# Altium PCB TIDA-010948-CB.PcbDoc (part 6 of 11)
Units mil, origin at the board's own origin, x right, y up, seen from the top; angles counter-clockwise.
Board outline 8100 x 8400 mil, 8 copper layers (L01 - TOP, L02 - GND, L03 - SIG, L04 - GND, L05 - PWR, L06 - SIG, L07 - GND, L08 - BOTTOM), stack 59.656 mil thick; 711 components, 572 nets, 2646 pads, 1325 vias.
Unrouted connection lines stored in the file: 988.
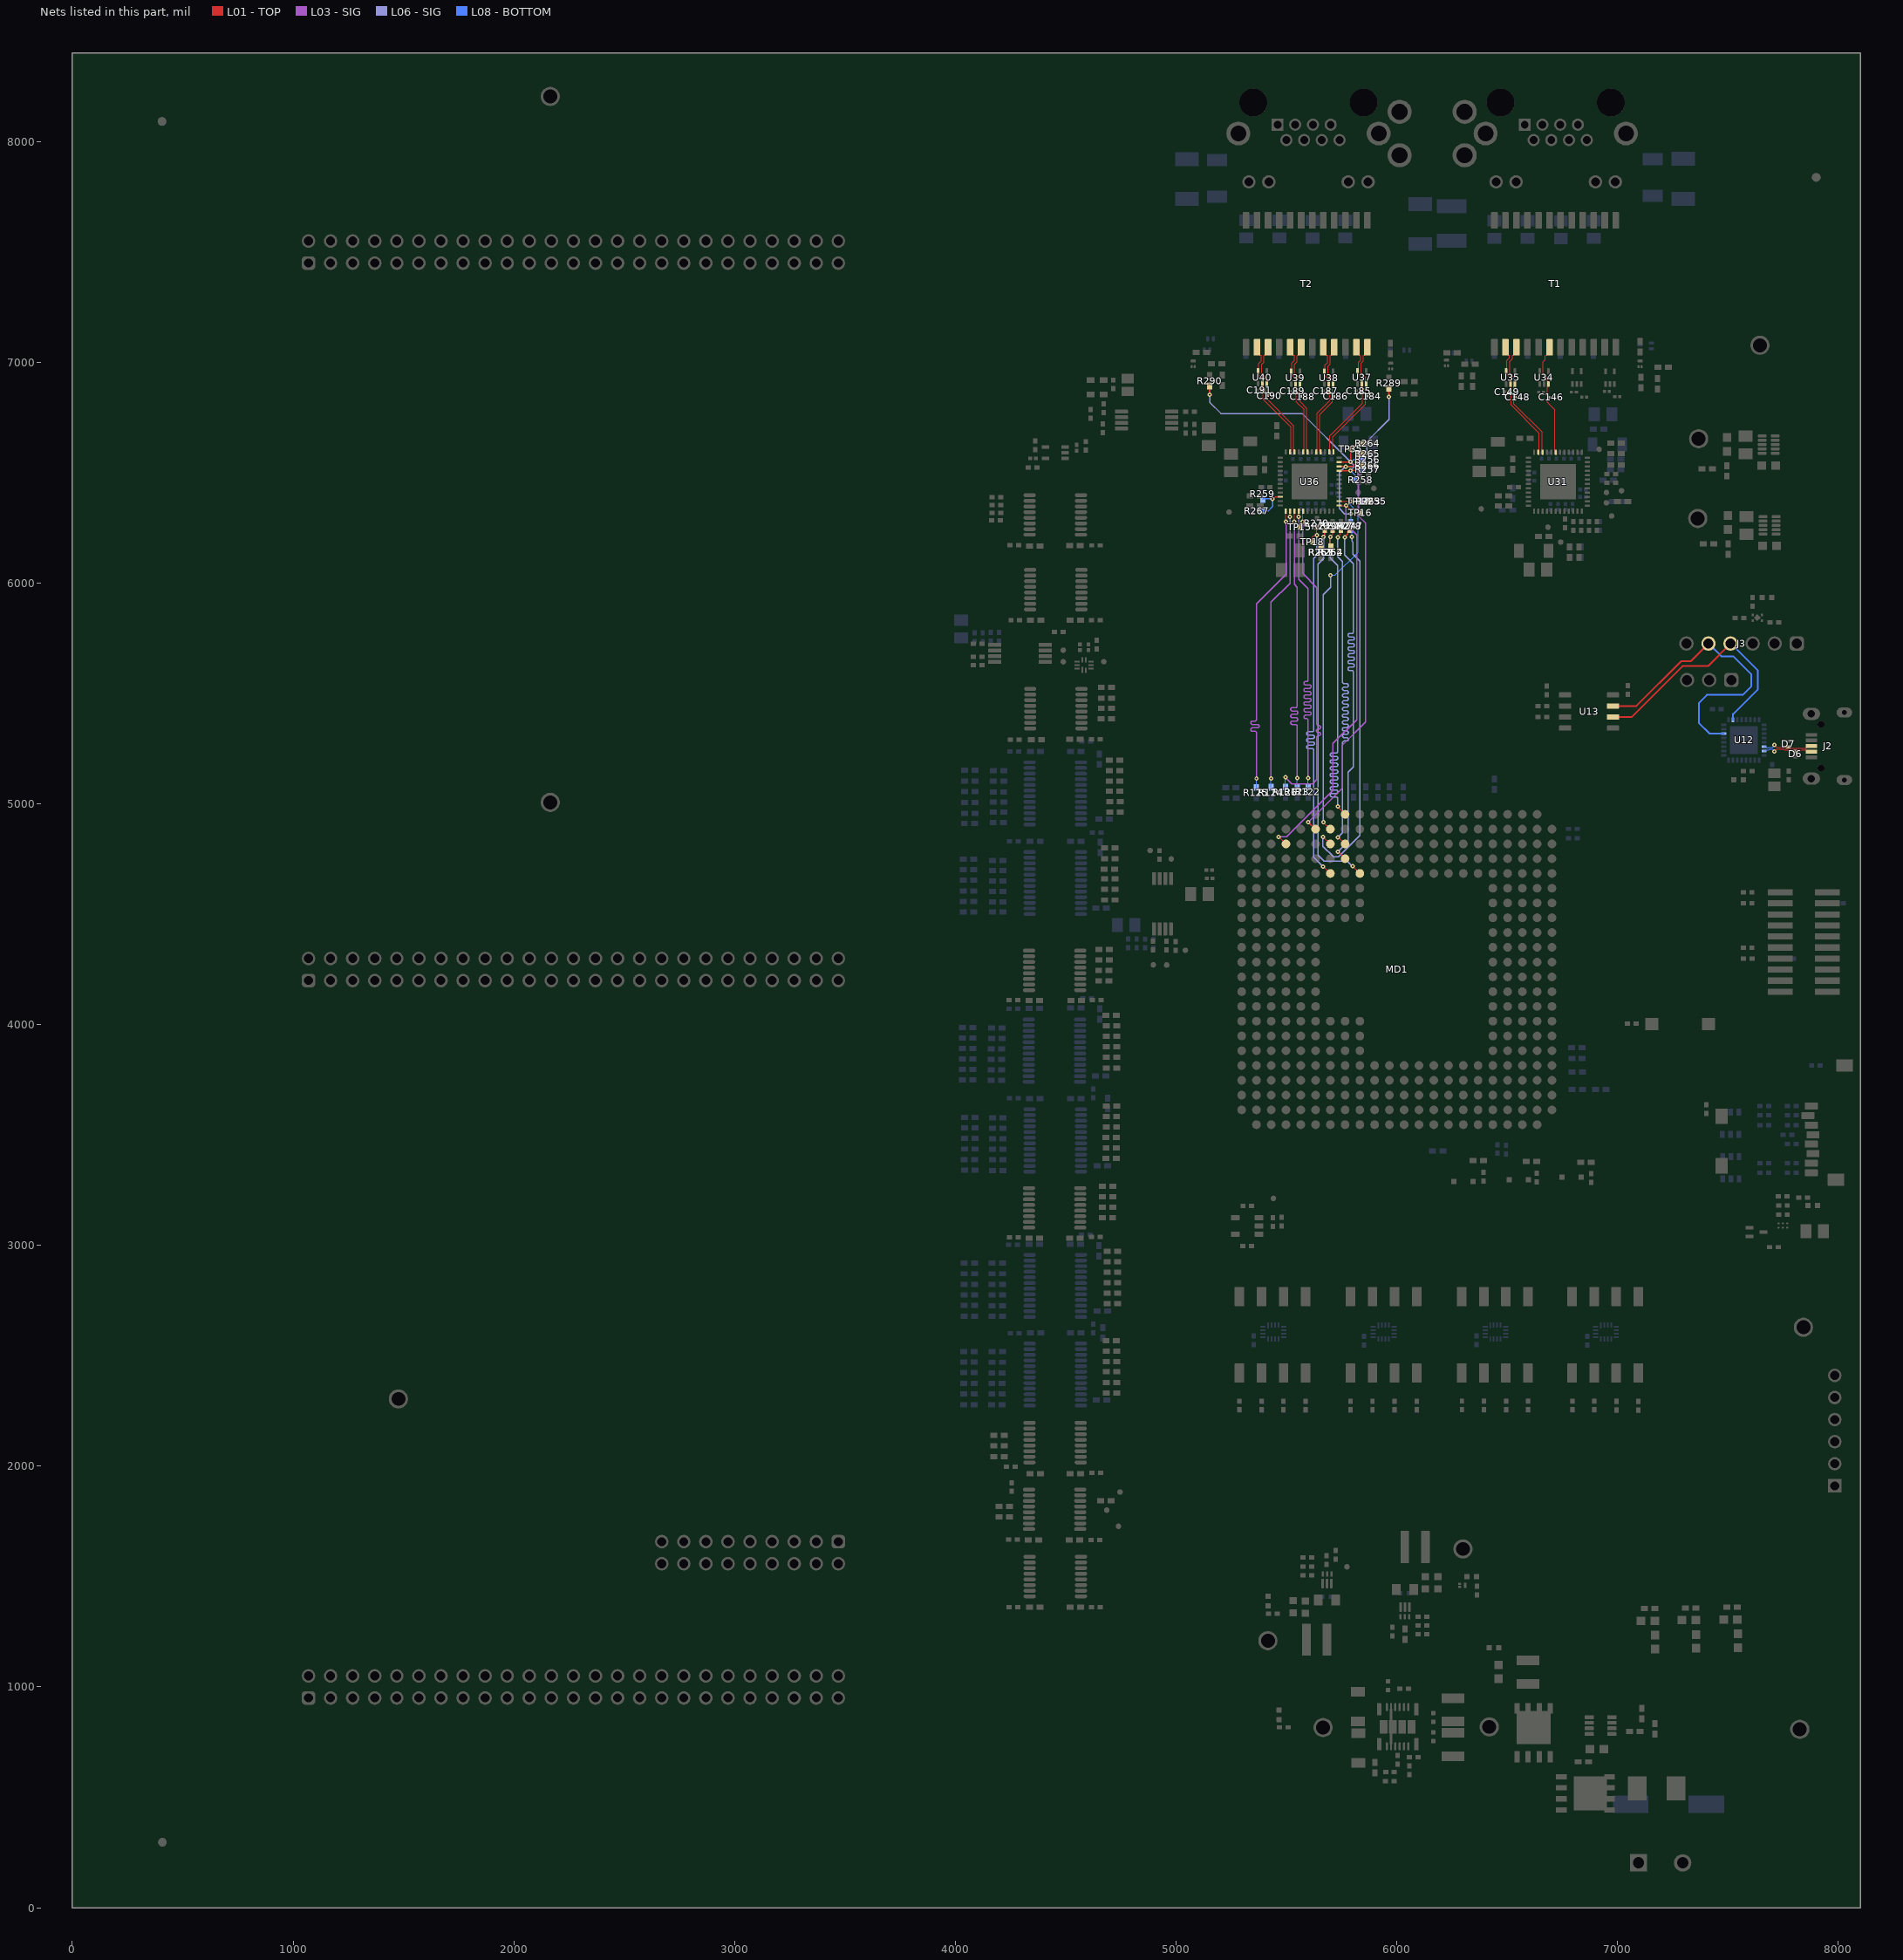
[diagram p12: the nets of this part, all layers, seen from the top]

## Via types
v1: diameter 19.68, hole 7.87, L01 - TOP to L08 - BOTTOM, 1310 vias
v2: diameter 20, hole 7.87, L01 - TOP to L08 - BOTTOM, tented both sides, 7 vias
v3: diameter 200, hole 144, L01 - TOP to L08 - BOTTOM, 6 vias
v4: diameter 20, hole 8, L01 - TOP to L08 - BOTTOM, tented both sides, 2 vias

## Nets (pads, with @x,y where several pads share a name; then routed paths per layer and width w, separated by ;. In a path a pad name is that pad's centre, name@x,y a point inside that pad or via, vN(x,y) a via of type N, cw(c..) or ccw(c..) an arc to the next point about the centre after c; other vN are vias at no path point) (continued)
ETH1_TD_C_P: C146.2 T1.6 U31.7 U34.3 | length 534.9
  L01 - TOP w3.5: U34.3@6682.5,6901.37 C146.2@6682.5,6841.5 ; U34.3@6686.19,6901.37 6682.56,6901.37 6682.5,6901.42 6682.5,6927 6662.5,6947 6662.5,7001.57 6673.25,7012.32 6673.25,7030.4 6675.3,7032.45 6678.8,7032.45 6692,7045.65 T1.6@6692,7067.5 ; C146.2@6688.48,6841.5 C146.2@6682.5,6841.5 ; C146.2@6682.5,6841.5 6682.5,6818 6716.56,6783.94 6716.56,6604.97 U31.7@6717.33,6604.21 ; U31.7@6717.33,6595.69 U31.7@6720.16,6592.86 U31.7@6717.33,6595.69 ; U31.7@6717.33,6595.69 U31.7@6717.33,6604.21 ; U31.7@6717.33,6595.69 U31.7@6717.33,6604.21
ETH1_TD_D_N: C149.2 T1.2 U31.11 U35.2 U35.5 | length 577.5
  L01 - TOP w3.5: T1.2@6492,7067.5 6492,7045.65 6505.2,7032.45 6508.7,7032.45 6510.75,7030.4 6510.75,7020.5 6499,7008.75 U35.5@6499,6959.58 ; U35.5@6494.81,6959.63 6494.87,6959.58 U35.5@6499,6959.58 ; C149.2@6512.02,6866 C149.2@6518,6866 ; U35.2@6514.5,6901.37 6514.56,6901.42 U35.2@6518,6901.42 ; U35.5@6499,6959.58 6499,6944.32 6518,6925.32 U35.2@6518,6901.42 ; C149.2@6518,6866 U35.2@6518,6901.42 ; C149.2@6518,6866 6518,6805.82 6645.01,6678.81 6645.01,6604.97 U31.11@6644.25,6604.21 ; U31.11@6644.25,6595.69 U31.11@6641.42,6592.86 U31.11@6644.25,6595.69 ; U31.11@6644.25,6595.69 U31.11@6644.25,6604.21 ; U31.11@6644.25,6595.69 U31.11@6644.25,6604.21
ETH1_TD_D_P: C148.2 T1.3 U31.10 U35.3 | length 573.4
  L01 - TOP w3.5: U35.3@6530.5,6901.37 C148.2@6530.5,6843 ; U35.3@6534.19,6901.37 6530.56,6901.37 6530.5,6901.42 6530.5,6930.5 6511.5,6949.5 6511.5,7003.57 6523.25,7015.32 6523.25,7030.4 6525.3,7032.45 6528.8,7032.45 6542,7045.65 T1.3@6542,7067.5 ; C148.2@6536.48,6843 C148.2@6530.5,6843 ; C148.2@6530.5,6843 6530.5,6811 6657.51,6683.99 6657.51,6604.97 U31.10@6658.27,6604.21 ; U31.10@6658.27,6595.69 U31.10@6661.1,6592.86 U31.10@6658.27,6595.69 ; U31.10@6658.27,6595.69 U31.10@6658.27,6604.21 ; U31.10@6658.27,6595.69 U31.10@6658.27,6604.21
ETH2_GPIO_1: R259.1 R267.2 U36.22 | length 173.3
  L01 - TOP w6: v1(5437,6381) 5440.7,6381 5450.28,6390.57 U36.22@5471.28,6390.57
  L08 - BOTTOM w6: R267.2@5389.62,6326 5416.5,6326 5437,6346.5 v1(5437,6381) 5394.62,6381 R259.1@5393,6379.38
ETH2_LED_0: MD1.B6 R256.1 R264.2 R290.1 TP35.1 U36.47 | length 2871.7
  L01 - TOP w6: v1(5599,4916.5) 5599.91,4916.5 5630.98,4885.43 MD1.B6@5631.89,4885.43 ; U36.47@5739.03,6548.03 v1(5791,6548) v1@5789.5,6549.5 ; v1(5791,6548) 5791.25,6548.25 5791.25,6606.25 TP35.1@5791.5,6606.5 5817.5,6632.5 R264.2@5844.88,6632.5
  L01 - TOP w8: v1(5152.5,6853) 5152.75,6853.25 5152.75,6891.63 R290.1@5153,6891.88
  L03 - SIG w6: v1(5599,4916.5) 5754.5,5072 5754.5,5266.54 5858,5370.04 5858,6272 5825.81,6304.19 5825.81,6513.19 v1(5791,6548)
  L06 - SIG w6: v1(5152.5,6853) 5152.5,6818.5 5203,6768 5571,6768 v1(5791,6548)
  L08 - BOTTOM w6: v1(5791,6548) 5793.65,6548 5805.65,6560 R256.1@5844.38,6560
ETH2_LED_1: R247.1 R257.1 R265.2 U36.46 | length 527.5
  L01 - TOP w6: U36.46@5739,6528.37 5739.19,6528.19 5768.31,6528.19 v1(5768.5,6528) 5769.5,6529 5802,6529 5812,6539 5812,6556 5818.5,6562.5 5818.5,6574.5 5820.69,6576.69 5835.57,6576.69 R265.2@5844.38,6585.5
  L06 - SIG w5.25: v1(5768.5,6528) 5740.03,6499.53 5740.03,6337.47 5764,6313.5 v1(5792.5,6313.5)
  L08 - BOTTOM w4.25: R247.1@5792,6278.69 5792.5,6279.19 v1(5792.5,6313.5)
  L08 - BOTTOM w6: v1(5768.5,6528) 5805.57,6528 5818.79,6514.78 5844.16,6514.78 R257.1@5844.38,6515
ETH2_LED_2: R258.1 R266.2 R289.1 U36.45 | length 614.7
  L01 - TOP w6: U36.45@5739,6508.69 5739.41,6509.09 5789.59,6509.09 v1(5790,6509.5) 5811.5,6509.5 5821,6519 5821,6523 5821.19,6523.19 5836.07,6523.19 R266.2@5844.88,6532
  L01 - TOP w8: R289.1@5964.5,6881.88 5964.75,6881.63 5964.75,6842.75 v1(5965,6842.5)
  L06 - SIG w6: v1(5790,6509.5) 5863.81,6583.31 5863.81,6639.81 5965,6741 v1(5965,6842.5)
  L08 - BOTTOM w6: v1(5790,6509.5) 5812.38,6487.12 R258.1@5812.38,6467
ETH2_RGMII2_RD0: MD1.E9 R253.1 R261.2 R273.1 | length 1808.7
  L01 - TOP w4.25: v1(5800,4717) 5800.16,4717 5832.52,4684.64 MD1.E9@5832.68,4684.64
  L01 - TOP w5.25: v1(5668,6208.5) 5668,6212.41 5673,6217.41 R273.1@5673,6238.31
  L01 - TOP w6: R261.2@5656.5,6162.62 5658.5,6164.62 5658.5,6195.3 5668,6204.8 v1(5668,6208.5)
  L06 - SIG w5.25: v1(5668,6208.5) 5668,6111.69 5642.83,6086.52 5642.83,4767.93 5670.13,4740.64 5776.36,4740.64 v1(5800,4717)
  L08 - BOTTOM w6: R253.1@5658.5,6161.62 5658.5,6195.3 5668,6204.8 v1(5668,6208.5)
ETH2_RGMII2_RD1: MD1.A8 R254.1 R262.2 R274.1 | length 1805.9
  L01 - TOP w4.25: v1(5699,6208.5) 5699,6210.13 5709.5,6220.63 R274.1@5709.5,6238.81 ; v1(5732,4987.5) 5732,4986.8 MD1.A8@5764.75,4954.05
  L01 - TOP w6: v1(5699,6208.5) 5699,6164.62 R262.2@5700.5,6163.12 ; MD1.A8@5764.75,4954.05 5764.75,4953.36 MD1.A8@5765.75,4952.36
  L06 - SIG w5.25: v1(5699,6208.5) 5699,6112.91 5732,6079.91 5732,5276.61 5732,5237.34 cw(c5724.38,5237.34) 5724.38,5229.72 5705.88,5229.72 ccw(c5705.88,5222.09) 5705.88,5214.47 5725.41,5214.47 cw(c5725.41,5206.84) 5725.41,5199.22 5705.88,5199.22 ccw(c5705.88,5191.59) 5705.88,5183.97 5725.41,5183.97 cw(c5725.41,5176.34) 5725.41,5168.72 5705.88,5168.72 ccw(c5705.88,5161.09) 5705.88,5153.47 5725.41,5153.47 cw(c5725.41,5145.84) 5725.41,5138.22 5705.88,5138.22 ccw(c5705.88,5130.59) 5705.88,5122.97 5725.41,5122.97 cw(c5725.41,5115.34) 5725.41,5107.72 5705.88,5107.72 ccw(c5705.88,5100.09) 5705.88,5092.47 5725.41,5092.47 cw(c5725.41,5084.84) 5725.41,5077.22 5705.88,5077.22 ccw(c5705.88,5069.59) 5705.88,5061.97 5725.41,5061.97 cw(c5725.41,5054.34) 5725.41,5046.72 5705.88,5046.72 ccw(c5705.88,5039.09) 5705.88,5031.47 5724.38,5031.47 cw(c5724.38,5023.84) 5732,5023.84 5732,5021.22 v1(5732,4987.5)
  L08 - BOTTOM w6: v1(5699,6208.5) 5699,6164.62 R254.1@5702,6161.62
ETH2_RGMII2_RD2: MD1.C8 R277.1 | length 1816.4
  L01 - TOP w4.25: v1(5732.5,6207.5) 5746.5,6221.5 R277.1@5746.5,6238.81 ; v1(5733.5,4848.5) 5734.62,4848.5 5764.63,4818.5 MD1.C8@5765.75,4818.5
  L06 - SIG w5.25: v1(5732.5,6207.5) 5732.5,6119.5 5754.5,6097.5 5754.5,5565.25 5754.5,5551.42 ccw(c5762.12,5551.42) 5762.12,5543.8 5772.8,5543.8 cw(c5772.8,5536.17) 5772.8,5528.55 5761.57,5528.55 ccw(c5761.57,5520.92) 5761.57,5513.3 5772.8,5513.3 cw(c5772.8,5505.67) 5772.8,5498.05 5761.57,5498.05 ccw(c5761.57,5490.42) 5761.57,5482.8 5772.8,5482.8 cw(c5772.8,5475.17) 5772.8,5467.55 5761.57,5467.55 ccw(c5761.57,5459.92) 5761.57,5452.3 5772.8,5452.3 cw(c5772.8,5444.67) 5772.8,5437.05 5761.57,5437.05 ccw(c5761.57,5429.42) 5761.57,5421.8 5772.8,5421.8 cw(c5772.8,5414.17) 5772.8,5406.55 5761.57,5406.55 ccw(c5761.57,5398.92) 5761.57,5391.3 5772.8,5391.3 cw(c5772.8,5383.67) 5772.8,5376.05 5761.57,5376.05 ccw(c5761.57,5368.42) 5761.57,5360.8 5772.8,5360.8 cw(c5772.8,5353.17) 5772.8,5345.55 5761.57,5345.55 ccw(c5761.57,5337.92) 5761.57,5330.3 5772.8,5330.3 cw(c5772.8,5322.67) 5772.8,5315.05 5761.57,5315.05 ccw(c5761.57,5307.42) 5761.57,5299.8 5772.8,5299.8 cw(c5772.8,5292.17) 5772.8,5284.55 5762.12,5284.55 ccw(c5762.12,5276.92) 5754.5,5276.92 5754.5,5259.05 5754.5,4869.5 v1(5733.5,4848.5)
ETH2_RGMII2_RD3: MD1.D8 R278.1 | length 1818.5
  L01 - TOP w4.25: v1(5733,4783) 5733.66,4783 5765.09,4751.57 MD1.D8@5765.75,4751.57
  L01 - TOP w5.25: v1(5764.5,6207.5) 5778.09,6221.09 5778.09,6231.37 R278.1@5785.31,6238.59
  L06 - SIG w5.25: v1(5733,4783) 5780,4830 5780,5144 5803.5,5167.5 5803.5,5593.49 5803.5,5596.11 ccw(c5795.88,5596.11) 5795.88,5603.74 5786.3,5603.74 cw(c5786.3,5611.36) 5786.3,5618.99 5800.25,5618.99 ccw(c5800.25,5626.61) 5800.25,5634.24 5786.3,5634.24 cw(c5786.3,5641.86) 5786.3,5649.49 5800.25,5649.49 ccw(c5800.25,5657.11) 5800.25,5664.74 5786.3,5664.74 cw(c5786.3,5672.36) 5786.3,5679.99 5800.25,5679.99 ccw(c5800.25,5687.61) 5800.25,5695.24 5786.3,5695.24 cw(c5786.3,5702.86) 5786.3,5710.49 5800.25,5710.49 ccw(c5800.25,5718.11) 5800.25,5725.74 5786.3,5725.74 cw(c5786.3,5733.36) 5786.3,5740.99 5800.25,5740.99 ccw(c5800.25,5748.61) 5800.25,5756.24 5786.3,5756.24 cw(c5786.3,5763.86) 5786.3,5771.49 5795.88,5771.49 ccw(c5795.88,5779.11) 5803.5,5779.11 5803.5,5792.75 5803.5,6087.5 5764.5,6126.5 v1(5764.5,6207.5)
ETH2_RGMII2_RX_CTL: MD1.B7 R255.1 R263.2 TP17.1 U36.38 | length 1783.6
  L01 - TOP w4.25: v1(5667,4917) 5667.12,4917 5698.7,4885.43 MD1.B7@5698.82,4885.43 ; U36.38@5739,6370.89 5739.06,6370.94 5790.94,6370.94 v1(5791,6371) 5791.25,6370.75 5825.75,6370.75 TP17.1@5826,6370.5 5872.88,6370.5 R255.1@5873.38,6370
  L06 - SIG w5.25: v1(5667,4917) 5667,5948 5699.5,5980.5 v1(5699.5,6036)
  L08 - BOTTOM w4.25: v1(5699.5,6036) 5720.5,6036 5824,6139.5 5824,6319.87 5791,6352.87 v1(5791,6371)
  L08 - BOTTOM w8: v1(5791,6371) 5791.38,6370.62 5849.13,6370.62 R263.2@5849.51,6370.25
ETH2_RGMII2_RX_ER: MD1.C7 R247.2 | length 1713.5
  L01 - TOP w4.25: v1(5665.5,4849) 5666.91,4849 5697.41,4818.5 MD1.C7@5698.82,4818.5
  L06 - SIG w5.25: v1(5665.5,4849) 5665.5,4808.13 5713.98,4759.66 5735.49,4759.66 5832.5,4856.67 5832.5,6098.5 5800.53,6130.47 5800.53,6185.52 5796.8,6189.25 v1(5796.8,6209.11)
  L08 - BOTTOM w4.25: R247.2@5792,6239.31 5796.8,6234.51 v1(5796.8,6209.11)
ETH2_RGMII2_RXC: MD1.E7 R270.1 TP18.1 | length 1818.5
  L01 - TOP w4.25: TP18.1@5617.5,6186 5617.5,6209 5623,6214.5 5636,6214.5 v1(5637.5,6216) R270.1@5637.5,6251.81 ; v1(5665.5,4716) 5666.48,4716 5697.84,4684.64 MD1.E7@5698.82,4684.64
  L06 - SIG w5.25: v1(5637.5,6216) 5637.5,6125.65 5624,6112.15 5624,5346.37 5624,5333.84 cw(c5616.38,5333.84) 5616.38,5326.21 5598.8,5326.21 ccw(c5598.8,5318.59) 5598.8,5310.96 5618.89,5310.96 cw(c5618.89,5303.34) 5618.89,5295.71 5598.8,5295.71 ccw(c5598.8,5288.09) 5598.8,5280.46 5618.89,5280.46 cw(c5618.89,5272.84) 5618.89,5265.21 5598.8,5265.21 ccw(c5598.8,5257.59) 5598.8,5249.96 5616.38,5249.96 cw(c5616.38,5242.34) 5624,5242.34 5624,5239.71 5624,4757.5 v1(5665.5,4716)
ETH2_RGMII2_TD0: R122.1 U36.28 | length 1550.7
  L01 - TOP w4.25: v1(5556,6299.5) v1(5556,6299.5) U36.28@5555.96,6325.58 ; U36.28@5555.93,6325.61 U36.28@5555.96,6325.58
  L03 - SIG w5.25: v1(5556,6299.5) 5555.53,6299.03 5555.53,6016.97 5598,5974.5 5598,5572.72 5598,5561.43 cw(c5590.38,5561.43) 5590.38,5553.81 5586.92,5553.81 ccw(c5586.92,5546.18) 5586.92,5538.56 5604.23,5538.56 cw(c5604.23,5530.93) 5604.23,5523.31 5586.92,5523.31 ccw(c5586.92,5515.68) 5586.92,5508.06 5604.23,5508.06 cw(c5604.23,5500.43) 5604.23,5492.81 5586.92,5492.81 ccw(c5586.92,5485.18) 5586.92,5477.56 5604.23,5477.56 cw(c5604.23,5469.93) 5604.23,5462.31 5586.92,5462.31 ccw(c5586.92,5454.68) 5586.92,5447.06 5604.23,5447.06 cw(c5604.23,5439.43) 5604.23,5431.81 5586.92,5431.81 ccw(c5586.92,5424.18) 5586.92,5416.56 5604.23,5416.56 cw(c5604.23,5408.93) 5604.23,5401.31 5586.92,5401.31 ccw(c5586.92,5393.68) 5586.92,5386.06 5590.38,5386.06 cw(c5590.38,5378.43) 5598,5378.43 5598,5375.81 v1(5598,5117.5)
  L08 - BOTTOM w4.25: R122.1@5598,5077.12 v1(5598,5117.5)
ETH2_RGMII2_TD1: R123.1 U36.27 | length 1402.3
  L01 - TOP w4.25: v1(5536,6278) 5536.12,6278.12 5536.12,6325.49 U36.27@5536.24,6325.61
  L03 - SIG w5.25: v1@5536.06,6278.06 v1(5536,6278) 5536,5994 5548.5,5981.5 5548.5,5460.77 5548.5,5443.38 cw(c5540.88,5443.38) 5540.88,5435.75 5526.71,5435.75 ccw(c5526.71,5428.13) 5526.71,5420.5 5543.69,5420.5 cw(c5543.69,5412.88) 5543.69,5405.25 5526.71,5405.25 ccw(c5526.71,5397.63) 5526.71,5390 5543.69,5390 cw(c5543.69,5382.38) 5543.69,5374.75 5526.71,5374.75 ccw(c5526.71,5367.13) 5526.71,5359.5 5540.88,5359.5 cw(c5540.88,5351.88) 5548.5,5351.88 5548.5,5349.25 v1(5548.5,5117.5)
  L08 - BOTTOM w4.25: R123.1@5548.5,5077.12 v1(5548.5,5117.5)
ETH2_RGMII2_TD2: R124.1 U36.26 | length 1286.8
  L01 - TOP w4.25: v1(5516.5,6300) U36.26@5516.53,6325.58
  L03 - SIG w5.25: v1(5430.5,5114.5) 5430.5,5387 5430.5,5557.77 5430.5,5913.5 5516.5,5999.5 v1(5516.5,6300)
  L08 - BOTTOM w4.25: R124.1@5430,5074.62 5430.5,5075.12 v1(5430.5,5114.5)
ETH2_RGMII2_TD3: R125.1 U36.25 | length 1408.9
  L01 - TOP w4.25: U36.25@5496.87,6325.61 5497.44,6325.05 5497.44,6278.56 v1(5498,6278)
  L03 - SIG w5.25: v1(5364.5,5114) 5364.5,5318.69 5364.5,5321.32 ccw(c5356.88,5321.32) 5356.88,5328.94 5346.18,5328.94 cw(c5346.18,5336.57) 5346.18,5344.19 5368.51,5344.19 ccw(c5368.51,5351.82) 5368.51,5359.44 5346.18,5359.44 cw(c5346.18,5367.07) 5346.18,5374.69 5356.88,5374.69 ccw(c5356.88,5382.32) 5364.5,5382.32 5364.5,5418.53 5364.5,5906.5 5498,6040 v1(5498,6278) v1@5497.72,6278.28
  L08 - BOTTOM w4.25: R125.1@5363.5,5074.12 5364.5,5075.12 v1(5364.5,5114)
ETH2_RGMII2_TX_CTL: MD1.C4 TP16.1 U36.37 | length 1846.6
  L01 - TOP w4.25: v1(5463.5,4850.5) 5464.76,4850.5 5496.77,4818.5 MD1.C4@5498.03,4818.5 ; U36.37@5739,6351.2 5739.1,6351.1 v1(5770.4,6351.1) 5784.49,6337.01 5804.01,6337.01 5815.99,6337.01 TP16.1@5835,6318
  L03 - SIG w5.25: v1(5463.5,4850.5) 5500.83,4850.5 5710,5059.67 5710,5273 5818,5381 5818,6217.53 5770.4,6265.13 v1(5770.4,6351.1)
ETH2_RGMII2_TXC: R126.1 TP15.1 U36.29 | length 1526.3
  L01 - TOP w4.25: TP15.1@5560,6253.5 5573,6266.5 v1(5573,6278) 5574.31,6279.31 5574.31,6324.31 U36.29@5575.61,6325.61
  L03 - SIG w5.25: v1(5495,5120) 5525,5090 5618.5,5090 5638,5109.5 5638,5283.12 5638,5301 cw(c5645.62,5301) 5645.62,5308.62 5646.86,5308.62 ccw(c5646.86,5316.25) 5646.86,5323.87 5643.15,5323.87 cw(c5643.15,5331.5) 5643.15,5339.12 5646.86,5339.12 ccw(c5646.86,5346.75) 5646.86,5354.37 5645.62,5354.37 cw(c5645.62,5362) 5638,5362 5638,5397.13 5638,5978.87 5573,6043.87 v1(5573,6278)
  L08 - BOTTOM w4.25: v1(5495,5120) 5495,5076.62 R126.1@5495.5,5076.12
ETH2_TD_A_N: C185.2 T2.11 U36.2 U37.2 U37.5 | length 572.1
  L01 - TOP w3.5: U36.2@5693.72,6593.33 5696.55,6596.16 5696.55,6604.68 5697.32,6605.44 5697.32,6666.82 5845.5,6815 C185.2@5845.5,6870 ; T2.11@5817,7067.5 5817,7045.65 5830.2,7032.45 5833.7,7032.45 5835.75,7030.4 5835.75,7010.5 5826,7000.75 U37.5@5826,6960.13 ; U37.5@5822.31,6960.13 5825.94,6960.13 5826,6960.08 5826,6945.32 5845.5,6925.82 5845.5,6901.92 5845.44,6901.87 U37.2@5842,6901.87 ; C185.2@5839.52,6870 C185.2@5845.5,6870 ; U37.2@5845.5,6901.87 C185.2@5845.5,6870
ETH2_TD_A_P: C184.2 T2.12 U36.1 U37.3 | length 568.6
  L01 - TOP w3.5: U36.1@5713.41,6593.33 5710.58,6596.16 5710.58,6604.68 5709.82,6605.44 5709.82,6661.64 5858,6809.82 C184.2@5858,6846.5 ; U37.3@5858,6901.87 C184.2@5858,6846.5 ; U37.3@5861.69,6901.87 5858.06,6901.87 5858,6901.92 5858,6931 5838.5,6950.5 5838.5,6995.57 5848.25,7005.32 5848.25,7030.4 5850.3,7032.45 5853.8,7032.45 5867,7045.65 T2.12@5867,7067.5 ; C184.2@5863.98,6846.5 C184.2@5858,6846.5
ETH2_TD_B_N: C187.2 T2.8 U36.5 U38.2 U38.5 | length 534.7
  L01 - TOP w3.5: U36.5@5634.67,6593.33 5637.5,6596.16 5637.5,6604.68 5638.26,6605.44 5638.26,6768.9 5695.59,6826.23 C187.2@5695.59,6869.5 ; T2.8@5667,7067.5 5667,7045.65 5680.2,7032.45 5683.7,7032.45 5685.75,7030.4 5685.75,6998.25 5675.66,6988.16 U38.5@5675.66,6959.08 ; U38.5@5672.31,6959.13 5672.37,6959.08 U38.5@5675.66,6959.08 ; C187.2@5689.52,6869.5 C187.2@5695.59,6869.5 ; U38.2@5692,6900.87 5695.53,6900.87 5695.59,6900.92 5695.59,6919.31 5675.66,6939.24 U38.5@5675.66,6959.08 ; U38.2@5695.59,6900.87 C187.2@5695.59,6869.5
ETH2_TD_B_P: C186.2 T2.9 U36.4 U38.3 | length 531.1
  L01 - TOP w3.5: U36.4@5654.35,6593.33 5651.52,6596.16 5651.52,6604.68 5650.76,6605.44 5650.76,6763.72 5708.09,6821.05 C186.2@5708.09,6845.5 ; U38.3@5708.09,6900.87 C186.2@5708.09,6845.5 ; U38.3@5711.69,6900.87 5708.15,6900.87 5708.09,6900.92 5708.09,6924.48 5688.16,6944.41 5688.16,6982.98 5698.25,6993.07 5698.25,7030.4 5700.3,7032.45 5703.8,7032.45 5717,7045.65 T2.9@5717,7067.5 ; C186.2@5713.98,6845.5 C186.2@5708.09,6845.5
ETH2_TD_C_N: C189.2 T2.5 U36.8 U39.2 U39.5 | length 525.5
  L01 - TOP w3.5: T2.5@5517,7067.5 5517,7045.65 5530.2,7032.45 5533.7,7032.45 5535.75,7030.4 5535.75,7007.25 5524.66,6996.16 U39.5@5524.66,6959.08 ; U39.5@5521.31,6959.13 5521.37,6959.08 U39.5@5524.66,6959.08 ; C189.2@5539.52,6869 C189.2@5545,6869 ; U39.2@5541,6900.87 5544.94,6900.87 5545,6900.92 5545,6920.95 5524.66,6941.29 U39.5@5524.66,6959.08 ; U39.2@5545,6900.87 C189.2@5545,6869 ; U36.8@5575.61,6593.33 5578.44,6596.16 5578.44,6604.68 5579.21,6605.44 5579.21,6786.62 5545,6820.82 C189.2@5545,6869
ETH2_TD_C_P: C188.2 T2.6 U36.7 U39.3 | length 521.8
  L01 - TOP w3.5: U39.3@5560.69,6900.87 5560.63,6900.92 U39.3@5557.5,6900.92 ; C188.2@5563.48,6845 C188.2@5557.5,6845 ; T2.6@5567,7067.5 5567,7045.65 5553.8,7032.45 5550.3,7032.45 5548.25,7030.4 5548.25,7002.07 5537.16,6990.98 5537.16,6946.47 5557.5,6926.13 U39.3@5557.5,6900.92 ; U36.7@5595.3,6593.33 5592.47,6596.16 5592.47,6604.68 5591.71,6605.44 5591.71,6791.79 5557.5,6826 C188.2@5557.5,6845 ; C188.2@5557.5,6845 U39.3@5557.5,6900.92
ETH2_TD_D_N: C191.2 T2.2 U36.11 U40.2 U40.5 | length 563.5
  L01 - TOP w3.5: T2.2@5367,7067.5 5367,7045.65 5380.2,7032.45 5383.7,7032.45 5385.75,7030.4 5385.75,7006 5375,6995.25 U40.5@5375,6961.13 ; U40.5@5371.31,6961.13 U40.5@5375,6961.13 ; C191.2@5388.52,6873.5 C191.2@5394.66,6873.5 ; U40.2@5391,6902.87 U40.2@5394.66,6902.87 ; U36.11@5516.56,6593.33 5519.39,6596.16 5519.39,6604.68 5520.15,6605.44 5520.15,6706.85 5394.66,6832.34 C191.2@5394.66,6873.5 ; U40.5@5375,6961.13 5375,6942.32 5394.66,6922.66 U40.2@5394.66,6902.87 ; C191.2@5394.66,6873.5 U40.2@5394.66,6902.87
ETH2_TD_D_P: C190.2 T2.3 U36.10 U40.3 | length 559.4
  L01 - TOP w3.5: U40.3@5410.69,6902.87 U40.3@5407.16,6902.87 ; C190.2@5412.98,6849 C190.2@5407.16,6849 ; T2.3@5417,7067.5 5417,7045.65 5403.8,7032.45 5400.3,7032.45 5398.25,7030.4 5398.25,7000.82 5387.5,6990.07 5387.5,6947.5 5407.16,6927.84 U40.3@5407.16,6902.87 ; U36.10@5536.24,6593.33 5533.41,6596.16 5533.41,6604.68 5532.65,6605.44 5532.65,6712.03 5407.16,6837.52 C190.2@5407.16,6849 ; C190.2@5407.16,6849 U40.3@5407.16,6902.87
FTDI_RXD: J3.4 U12.2 U13.6 | length 1114.9
  L01 - TOP w8: U13.6@6979.27,5393 7063,5393 7294,5624 7410,5624 J3.4@7512,5726
  L08 - BOTTOM w8: J3.4@7512,5726 7513,5726 7636,5603 7636,5519 7523.25,5406.25 U12.2@7523.25,5380.38
FTDI_TXD: J3.5 U12.30 U13.7 | length 1348
  L01 - TOP w8: U13.7@6979.27,5443 7085.41,5443 7288.41,5646 7332,5646 J3.5@7412,5726
  L08 - BOTTOM w8: J3.5@7412,5726 7470,5668 7524,5668 7606,5586 7606,5531.69 7567.31,5493 7405,5493 7368,5456 7368,5367 7417,5318 7480.56,5318 U12.30@7480.93,5318.37
FTDI_USB_D_N: D6.1 J2.2 U12.15 | length 229.9
  L01 - TOP w4: v1(7711,5237.5) 7711,5237.75 7720.75,5247.5 7753.17,5247.5 7756.97,5243.7 D6.1@7806,5243.7 ; D6.1@7806,5238.3 D6.1@7806.03,5243.48 ; D6.1@7806.03,5243.7 7852.97,5243.7 7857.05,5239.63 J2.2@7873.78,5239.63
  L08 - BOTTOM w4: U12.15@7664,5239.63 7669.91,5239.63 7675.25,5244.97 7685.54,5244.97 7688.07,5247.5 7700.75,5247.5 7710.75,5237.5 v1(7711,5237.5)
FTDI_USB_D_P: D7.1 J2.3 U12.14 | length 236.2
  L01 - TOP w4: v1(7710.5,5266.5) 7710.75,5266.5 7720.75,5256.5 7756.9,5256.5 7760.7,5252.7 D7.1@7774,5252.7 ; D7.1@7774,5258.2 D7.1@7774,5252.7 ; J2.3@7878,5261 7861.27,5261 7852.97,5252.7 D7.1@7774,5252.7
  L08 - BOTTOM w4: U12.14@7664,5259.31 7669.91,5259.31 7675.25,5253.97 7681.81,5253.97 7684.34,5256.5 7700.75,5256.5 7710.5,5266.25 v1(7710.5,5266.5)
